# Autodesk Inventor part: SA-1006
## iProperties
Created: 2004-11
Part Number: SA-1006
Cost Center: 0 lbmass
Document SubType Name: Modeling
Designer: busseym
Manufacturer: Standard
Standards Organization: Custom
Stock Number: P-1267
Density: 1 g/cm^3
CAGE: 1LJX3
Dept. ID: Product Design
Description #2: ---
Finish #1: ---
Finish #2: ---
Material ID: ---
Project Number: ---
Author: busseym
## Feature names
1. Extrusion1
